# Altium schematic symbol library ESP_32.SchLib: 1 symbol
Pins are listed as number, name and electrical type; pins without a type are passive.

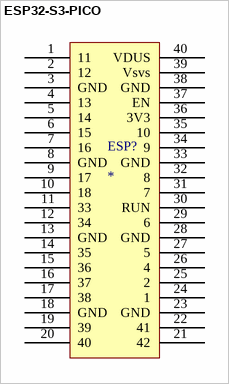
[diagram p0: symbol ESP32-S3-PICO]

## ESP32-S3-PICO
designator ESP?
footprint DIP40_ESP32
pins: 1 11, 2 12, 3 GND, 4 13, 5 14, 6 15, 7 16, 8 GND, 9 17, 10 18, 11 33, 12 34, 13 GND, 14 35, 15 36, 16 37, 17 38, 18 GND, 19 39, 20 40, 21 42, 22 41, 23 GND, 24 1, 25 2, 26 4, 27 5, 28 GND, 29 6, 30 RUN, 31 7, 32 8, 33 GND, 34 9, 35 10, 36 3V3, 37 EN, 38 GND, 39 Vsvs, 40 VDUS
